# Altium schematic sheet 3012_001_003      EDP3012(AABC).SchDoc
size A4
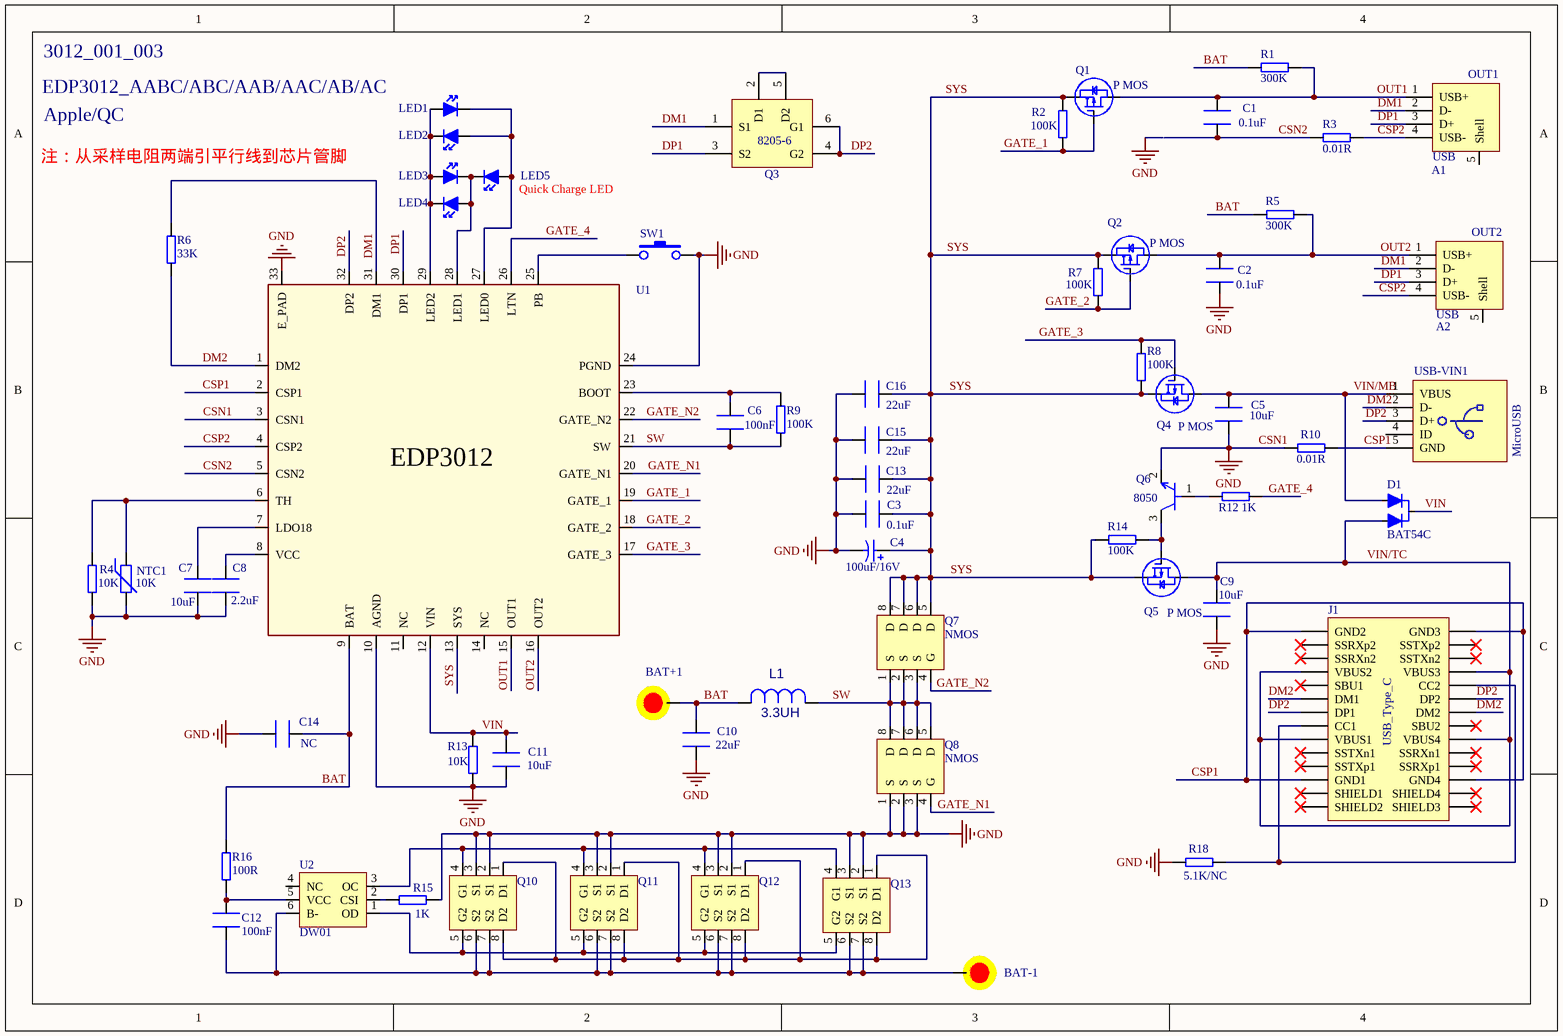
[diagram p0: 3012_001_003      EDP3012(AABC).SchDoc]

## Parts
BAT+1  TP  [BAT-2.54]  (value not drawn)
BAT-1  TP  [BAT-2.54]  (value not drawn)
C1  0.1uF  [C0603A]
C2  0.1uF  [C0603A]
C3  0.1uF  [C1206]
C4  100uF/16V
C5  10uF  [C0805A]
C6  100nF  [C0603A]
C7  10uF  [C0805A]
C8  2.2uF  [C0603A]
C9  10uF  [C0805A]
C10  22uF  [C0805A]
C11  10uF  [C0805A]
C12  100nF  [C0603A]
C13  22uF  [C1206]
C14  NC  [C0805A]
C15  22uF  [C1206]
C16  22uF  [C1206]
D1  BAT54C  [SOT-23]
J1  USB_Type_C  [TYPE-C]
L1  value 3.3UH  [L_MS1040]  (hidden comment: CDH73(10uH))
LED1  LED_B  [0603_LED_B]  (value not drawn)
LED2  LED_B  [0603_LED_B]  (value not drawn)
LED3  LED_B  [0603_LED_B]  (value not drawn)
LED4  LED_B  [0603_LED_B]  (value not drawn)
LED5  LED_B  [0603_LED_B]  (value not drawn)
NTC1  10K  [NTC-1]
OUT1  USB  [USB-A-C]
OUT2  USB  [USB-A-C]
Q1  P MOS  [SOT-23]
Q2  P MOS  [SOT-23]
Q3  8205-6  [SOT23-6]
Q4  P MOS  [SOT-23]
Q5  P MOS  [SOT-23]
Q6  8050  [SOT-23]
Q7  NMOS  [DFN3.3*3.3]
Q8  NMOS  [DFN3.3*3.3]
Q10  (no value)  [TSSOP-8]
Q11  (no value)  [TSSOP-8]
Q12  (no value)  [TSSOP-8]
Q13  (no value)  [TSSOP-8]
R1  300K  [R0603A]
R2  100K  [R0603A]
R3  0.01R  [R1206A]
R4  10K  [R0603A]
R5  300K  [R0603A]
R6  33K  [R0603A]
R7  100K  [R0603A]
R8  100K  [R0603A]
R9  100K  [R0603A]
R10  0.01R  [R1206A]
R12  1K  [R0603A]
R13  10K  [R0603A]
R14  100K  [R0603A]
R15  1K  [R0603A]
R16  100R  [R0603A]
R18  5.1K/NC  [R0603A]
SW1  SW  [KEY-6*3.5]  (value not drawn)
U1  EDP3012  [QFN50P500X500X90-32N]  (value not drawn)
U2  DW01  [SOT23-6]
USB-VIN1  MicroUSB  [M-USB_5.9MM]

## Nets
CSN1: C3.1 C4.2 C5.1 C7.1 C8.1 C9.1 C10.1 C11.1 C13.1 C14.2 C15.1 C16.1 NTC1.2 Q6.2(E) Q8.1(S) Q8.2(S) Q8.3(S) Q10.2(S1) Q10.3(S1) Q11.2(S1) Q11.3(S1) Q12.2(S1) Q12.3(S1) Q13.2(S1) Q13.3(S1) R4.2 R10.2 R13.2 R15.2 R18.1 SW1.2 U1.3(CSN1) U1.10(AGND) U1.24(PGND) U1.33(E_PAD)  [also labelled GND]
BAT: BAT+1.1 C10.2 C14.1 L1.1 R1.1 R5.1 R16.2 U1.9(BAT)
CSN2: C1.1 R3.1 U1.5(CSN2)
CSP1: J1.A1(GND1) J1.A12(GND2) J1.B1(GND3) J1.B12(GND4) R10.1 U1.2(CSP1) USB-VIN1.5(GND)
CSP2: OUT1.4(USB-) OUT2.4(USB-) R3.2 U1.4(CSP2)
DM1: OUT1.2(D-) OUT2.2(D-) Q3.1(S1) R6.1 U1.31(DM1)
DM2: J1.A7(DM1) J1.B7(DM2) R6.2 U1.1(DM2) USB-VIN1.2(D-)
DP1: OUT1.3(D+) OUT2.3(D+) Q3.3(S2) U1.30(DP1)
DP2: J1.A6(DP1) J1.B6(DP2) Q3.4(G2) Q3.6(G1) U1.32(DP2) USB-VIN1.3(D+)
GATE_1: Q1.1(G) R2.2 U1.19(GATE_1)
GATE_2: Q2.1(G) R7.2 U1.18(GATE_2)
GATE_3: Q4.1(G) R8.1 U1.17(GATE_3)
GATE_4: R12.1 U1.26(LTN)
GATE_N1: Q8.4(G) U1.20(GATE_N1)
GATE_N2: Q7.4(G) U1.22(GATE_N2)
OUT1: C1.2 OUT1.1(USB+) Q1.3(D) R1.2 U1.15(OUT1)
OUT2: C2.2 OUT2.1(USB+) Q2.3(D) R5.2 U1.16(OUT2)
SW: C6.2 L1.2 Q7.1(S) Q7.2(S) Q7.3(S) Q8.5(D) Q8.6(D) Q8.7(D) Q8.8(D) R9.2 U1.21(SW)
SYS: C3.2 C4.1 C13.2 C15.2 C16.2 Q1.2(S) Q2.2(S) Q4.2(S) Q5.2(S) Q7.5(D) Q7.6(D) Q7.7(D) Q7.8(D) R2.1 R7.1 R8.2 R14.1 U1.13(SYS)
VIN: C11.2 D1.3(C) R13.1 U1.12(VIN)
VIN/MB: C5.2 D1.1(A) Q4.3(D) USB-VIN1.1(VBUS)
VIN/TC: C9.2 D1.2(B) J1.A4(VBUS1) J1.A9(VBUS2) J1.B4(VBUS3) J1.B9(VBUS4) Q5.3(D)
NetBAT-1_1: BAT-1.1 C12.1 Q10.6(S2) Q10.7(S2) Q11.6(S2) Q11.7(S2) Q12.6(S2) Q12.7(S2) Q13.6(S2) Q13.7(S2) U2.6(B-)
NetC6_1: C6.1 R9.1 U1.23(BOOT)
NetC7_2: C7.2 U1.7(LDO18)
NetC8_2: C8.2 U1.8(VCC)
NetC12_2: C12.2 R16.1 U2.5(VCC)
NetJ1_A5: J1.A5(CC1) J1.B5(CC2) R18.2
NetLED1_A: LED1.A LED2.K LED3.A LED4.K U1.29(LED2)
NetLED1_K: LED1.K LED2.A LED5.A U1.27(LED0)
NetLED3_K: LED3.K LED4.A LED5.K U1.28(LED1)
NetNTC1_1: NTC1.1 R4.1 U1.6(TH)
NetQ3_2: Q3.2(D1) Q3.5(D2)
NetQ5_1: Q5.1(G) Q6.3(C) R14.2
NetQ6_1: Q6.1(B) R12.2
NetQ10_1: Q10.1(D1) Q10.8(D2) Q11.1(D1) Q11.8(D2) Q12.1(D1) Q12.8(D2) Q13.1(D1) Q13.8(D2)
NetQ10_4: Q10.4(G1) Q11.4(G1) Q12.4(G1) Q13.4(G1) U2.3(OC)
NetQ10_5: Q10.5(G2) Q11.5(G2) Q12.5(G2) Q13.5(G2) U2.1(OD)
NetR15_1: R15.1 U2.2(CSI)
NetSW1_1: SW1.1 U1.25(PB)

Not connected (* = marked no-connect by the designer): C2 1; J1 0(SHIELD1)* A2(SSTXp1)* A3(SSTXn1)* A8(SBU1)* A10(SSRXn2)* A11(SSRXp2)* B2(SSTXp2)* B3(SSTXn2)* B8(SBU2)* B10(SSRXn1)* B11(SSRXp1)*; OUT1 5(Shell); OUT2 5(Shell); U1 11(NC) 14(NC); U2 4(NC); USB-VIN1 4(ID)

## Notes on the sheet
- EDP3012_AABC/ABC/AAB/AAC/AB/AC
- 3012_001_003
- 注：从采样电阻两端引平行线到芯片管脚
- Apple/QC
- (near OUT1) A1
- (near LED5) Quick Charge LED
- (near OUT2) A2
- Labels drawn without touching a wire or pin: GND

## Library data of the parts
C1-C3 C5-C16 = CAP: 贴片电容
C4 = CAP POL-1: Bi-Polar Capacitor
L1 = L\CDH73(S)
LED1-LED4 = L: 发光二极管
LED5 = LED-B: 发光二极管
NTC1 = Res Varistor: Varistor (Voltage-Sensitive Resistor)
Q1 Q2 Q4 Q5 = MOSFET P_s: 场效应管
Q3 = S8205-6P-3
Q6 = NPN-1: 3904
Q7 Q8 = MOS_SOP8
Q10-Q13 = S8205A
R1-R10 R12-R16 R18 = RES: 贴片电阻
SW1 = SW-PB: 中龟按键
